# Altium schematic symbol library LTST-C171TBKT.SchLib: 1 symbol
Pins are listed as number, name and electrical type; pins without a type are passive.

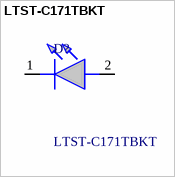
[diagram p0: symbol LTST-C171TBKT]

## LTST-C171TBKT
designator D?
LED,SMD,0805,Blue,28mcd,130deg Lite-On LTST-C171TBKT, CHIPLED 0805 Series Blue LED, 475 nm 2012 (0805), Rectangle Lens SMD package; Geometry.Height: 0.9mm
footprint LTSTC171TBKT
pins: 1 K, 2 A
